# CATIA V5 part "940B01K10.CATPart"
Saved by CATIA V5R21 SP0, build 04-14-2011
Part number: 940B01K10
Bounding box of the stored display mesh (mm): x -8.25 to 387.75, y -7 to 7, z -25.901 to 9.099
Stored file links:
  C:\Users\ALI OZGUN\Desktop\alhan\940B01K10.CATPart
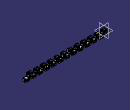
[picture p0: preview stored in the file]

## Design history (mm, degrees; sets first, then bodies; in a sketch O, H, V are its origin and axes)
Body1 (main body)
  Sketch1 on zx-plane, origin (0, 0, 0), H (-1, 0, 0), V (0, 0, 1)
    point P1 (-8.25, -8.9006)
    line L1 (-8.25, -7.9006) -> (-8, -7.6506)
    point P2 (-8, -7.6506)
    line L2 (-8, -7.6506) -> (-8, 6.6246)
    point P3 (-8, 6.6246)
    line L3 (-8, 6.6246) -> (-5.5251, 9.0994)
    point P4 (-5.5251, 9.0994)
    line L4 (-5.5251, 9.0994) -> (0, 9.0994)
    point P5 (0, 9.0994)
    line L5 (-8.25, -7.9006) -> (-8.25, -11.9006)
    point P6 (-8.25, -11.9006)
    line L6 (-8.25, -11.9006) -> (-5, -8.6506)
    point P7 (-3.25, -6.9006)
    line L7 (-5, -6.9006) -> (0, -6.9006)
    point P8 (0, -6.9006)
    line L8 (0, 6.2994) -> (-4.0825, 6.2994)
    point P9 (-4.0825, 6.2994)
    line L9 (-4.0825, 6.2994) -> (-5.2, 5.1819)
    point P10 (-5.2, 5.1819)
    line L10 (-5.2, 5.1819) -> (-5.2, -3.4006)
    point P11 (-5.2, -3.4006)
    line L11 (-5.2, -3.4006) -> (0, -3.4006)
    point P12 (0, -3.4006)
    point P13 (-8.25, -7.9006)
    point P14 (8, -7.6506)
    point P15 (8.25, -7.9006)
    line L12 (8.25, -7.9006) -> (8, -7.6506)
    point P16 (8, 6.6246)
    line L13 (8, -7.6506) -> (8, 6.6246)
    point P17 (5.5251, 9.0994)
    line L14 (8, 6.6246) -> (5.5251, 9.0994)
    point P18 (8.25, -11.9006)
    line L15 (8.25, -7.9006) -> (8.25, -11.9006)
    point P19 (3.25, -6.9006)
    line L16 (8.25, -11.9006) -> (5, -8.6506)
    point P20 (5.2, 5.1819)
    point P21 (4.0825, 6.2994)
    line L17 (4.0825, 6.2994) -> (5.2, 5.1819)
    point P22 (5.2, -3.4006)
    line L18 (5.2, 5.1819) -> (5.2, -3.4006)
    point P23 (0, -6.9006)
    line L19 (5, -6.9006) -> (0, -6.9006)
    point P24 (0, -3.4006)
    line L20 (5.2, -3.4006) -> (0, -3.4006)
    line L21 (0, 6.2994) -> (4.0825, 6.2994)
    point P25 (0, 9.0994)
    line L22 (5.5251, 9.0994) -> (0, 9.0994)
    point P26 (0, 6.2994)
    point P27 (0, 6.2994)
    line L23 (-5, -6.9006) -> (-5, -8.6506)
    line L24 (5, -6.9006) -> (5, -8.6506)
    distance L2 V = 8
    angle L3 L2 = 135
    distance L4 H = 9.0994
    distance L8 L4 = 2.8
    distance L10 L2 = 2.8
    distance L11 L7 = 3.5
    distance L9 L3 = 3
    length L3 = 3.5
    distance L4 L7 = 16
    distance L4 P6 = 21
    distance L5 L2 = 0.25
    length L5 = 4
    distance L23 L2 = 3
    vertical: L2 V, L5 V, L10 V, L23 V
    parallelism: L3 L1, L6 L1
    horizontal: L4 H, L7 H, L8 H, L11 H
    coincidence: P5 V, P8 V, P12 V, P1 L5, P26 V, P27 V, P5 P25, P8 P23, P12 P24, P26 P27, P7 L7, P7 L6, P19 L16, P19 L19
    symmetry: P2 P14 V, P13 P15 V, L1 L12 V, P3 P16 V, L2 L13 V, P4 P17 V, L3 L14 V, P6 P18 V, L5 L15 V, P7 P19 V, L6 L16 V, P10 P20 V, P9 P21 V, L9 L17 V, P11 P22 V, L10 L18 V, P8 P23 V, L7 L19 V, P12 P24 V, L11 L20 V, L8 L21 V, P5 P25 V, L4 L22 V, L23 L24 V
  Pad1: profile Sketch1, direction (0, 1, 0), length 7, mirrored extent
  Fillet1: radius 3, on edge [face of Pad1 from Sketch1.L22 | face of Pad1 from Sketch1.L14]; edge [face of Pad1 from Sketch1.L3 | face of Pad1 from Sketch1.L4]; edge [face of Pad1 from Sketch1.L2 | face of Pad1 from Sketch1.L3]; edge [face of Pad1 from Sketch1.L14 | face of Pad1 from Sketch1.L13]
  Fillet2: radius 1, on edge [face of Pad1 from Sketch1.L17 | face of Pad1 from Sketch1.L21]; edge [face of Pad1 from Sketch1.L18 | face of Pad1 from Sketch1.L17]; edge [face of Pad1 from Sketch1.L8 | face of Pad1 from Sketch1.L9]; edge [face of Pad1 from Sketch1.L9 | face of Pad1 from Sketch1.L10]
  Fillet3: radius 2, on edge [face of Pad1 from Sketch1.L23 | face of Pad1 from Sketch1.L6]; edge [face of Pad1 from Sketch1.L16 | face of Pad1 from Sketch1.L24]
  Fillet4: radius 1.5, on edge [face of Pad1 from Sketch1.L20 | face of Pad1 from Sketch1.L18]; edge [face of Pad1 from Sketch1.L10 | face of Pad1 from Sketch1.L11]
  Body2
    Sketch2 on zx-plane, origin (0, 0, 0), H (-1, 0, 0), V (0, 0, 1)
      line L1 (-8.25, -7.9006) -> (-10.25, -9.9006)
      line L2 (-10.25, -9.9006) -> (-16.5, -9.9006)
      line L3 (-8.25, -11.9006) -> (-8.5, -12.1506)
      line L4 (-8.5, -12.1506) -> (-8.5, -25.9006)
      line L5 (-8.5, -25.9006) -> (-16.5, -25.9006)
      line L6 (-16.5, -22.7006) -> (-11.3, -22.7006)
      line L7 (-11.3, -22.7006) -> (-11.3, -13.1006)
      line L8 (-11.3, -13.1006) -> (-16.5, -13.1006)
      axis line L9 (-16.5, -4.8689) -> (-16.5, -27.5881)
      point P6 (-16.5, -9.9006)
      point P7 (-16.5, -13.1006)
      point P8 (-16.5, -22.7006)
      point P9 (-16.5, -25.9006)
      reference projected line E1 (0, 9.0994) -> (-5.5251, 9.0994) from edge [face of Pad1 from Sketch1.L4 | end face of Pad1]
      reference projected line E2 (-8.325, -11.9756) -> (-4.925, -8.5756) from edge [face of Pad1 from Sketch1.L6 | end face of Pad1]
      reference projected line E3 (-7.925, -7.5756) -> (-8.325, -7.9756) from edge [face of Pad1 from Sketch1.L1 | end face of Pad1]
      projected line E4 (-8.25, -7.9006) -> (-8.25, -11.9006) from edge [face of Pad1 from Sketch1.L5 | end face of Pad1]
      projected line E5 (-8.25, -7.9006) -> (-8.25, -11.9006) from edge [face of Pad1 from Sketch1.L5 | end face of Pad1]
      reference projected line E6 (-8, 6.6246) -> (-8, -7.6506) from edge [face of Pad1 from Sketch1.L2 | end face of Pad1]
      line L10 (-16.5, -9.9006) -> (-16.5, -13.1006)
      line L11 (-16.5, -22.7006) -> (-16.5, -25.9006)
      distance L5 E1 = 35
      distance L2 L5 = 16
      distance L8 L2 = 3.2
      distance L6 L5 = 3.2
      distance L7 L4 = 2.8
      distance L4 E6 = 0.5
      distance L4 L9 = 8
      horizontal: L2 H, L5 H, L6 H, L8 H
      vertical: L4 V, L7 V, L9 V, L10 V, L11 V
      coincidence: P6 L9, P7 L9, P8 L9, P9 L9, L3 E2, L1 E3
    Pad2: profile Sketch2, direction (0, 1, 0), length 7, mirrored extent
    Mirror1: of the body so far, about face of Pad2 from Sketch2.L10
    Fillet5: radius 1.5, on edge [face of Pad2 | face of Mirror1] (x2); edge [face of Pad2 from Sketch2.L4 | face of Pad2]; edge [face of Mirror1 | face of Pad2] (x2); edge [face of Pad2 | face of Pad2 from Sketch2.L1]; edge [face of Pad2 from Sketch2.L7 | face of Pad2]; edge [face of Pad2 | face of Pad2 from Sketch2.L7]
  Add1: tool Body2
  RemoveFace1: RemoveFaces (face of Fillet5; face of Fillet1; face of Fillet5; face of Fillet1)
  Thickness1: Face (face of Pad2 from Sketch2.L4; face of Mirror1; face of Pad1 from Sketch1.L2; face of Pad1 from Sketch1.L13), Thickness 0.2
  RectPattern1: of the body so far, direction 1 instances 12, spacing 33, along edge [face of Pad1 | face of Pad2]
  Sketch3 on yz-plane, origin (0, 0, 0), H (0, 1, 0), V (0, 0, 1)
    construction line L1 (0, 4.5994) -> (0, -1.4006)
    point P1 (0, 4.5994)
    line L2 (2.5, 4.5994) -> (2.5, -1.4006)
    line L3 (-2.5, -1.4006) -> (-2.5, 4.5994)
    arc A1 centre (0, -1.4006) radius 2.5 from (2.5, -1.4006) to (-2.5, -1.4006) cw
    arc A2 centre (0, 4.5994) radius 2.5 from (-2.5, 4.5994) to (2.5, 4.5994) cw
    construction line L4 (0, -14.8006) -> (0, -20.8006)
    point P7 (0, -14.8006)
    point P8 (0, -20.8006)
    line L5 (2.5, -14.8006) -> (2.5, -20.8006)
    line L6 (-2.5, -20.8006) -> (-2.5, -14.8006)
    arc A3 centre (0, -20.8006) radius 2.5 from (2.5, -20.8006) to (-2.5, -20.8006) cw
    arc A4 centre (0, -14.8006) radius 2.5 from (-2.5, -14.8006) to (2.5, -14.8006) cw
    reference projected line E1 (-7, 9.0994) -> (7, 9.0994) from edge [face of Pad1 from Sketch1.L22 | face of Fillet1]
    distance L1 L2 = 2.5
    distance L4 L5 = 2.5
    length L1 = 6
    length L4 = 6
    distance A2 E1 = 2
    distance P8 P1 = 25.4
    coincidence: P1 V, P7 V
    vertical: L1 V, L4 V
    tangency: A1 L2, A2 L2, A1 L3, A2 L3, A3 L5, A4 L5, A3 L6, A4 L6
  Pocket1: profile Sketch3, direction (-1, 0, 0), through (limit type 3), opposite side through (limit type 3)
  Sketch4 on yz-plane, origin (0, 0, 0), H (0, 1, 0), V (0, 0, 1)
    point P1 (-8.4771, 2.8138)
    line L1 (-8.4771, 2.8138) -> (-2.6189, 9.5743)
    point P2 (-2.6189, 9.5743)
    line L2 (-2.6189, 9.5743) -> (2.2825, 9.5743)
    point P3 (2.2825, 9.5743)
    line L3 (2.2825, 9.5743) -> (8.6297, 3.2271)
    point P4 (8.6297, 3.2271)
    reference projected line E1 (-7, 9.0994) -> (-7, 8.2208) from edge [face of RectPattern1 | face of RectPattern1]
    point P5 (-7, 9.0994)
    point P6 (-7, 8.2208)
    reference projected line E2 (7, 8.2208) -> (7, 9.0994) from edge [face of RectPattern1 | face of RectPattern1]
    point P7 (7, 8.2208)
    point P8 (7, 9.0994)
    reference projected line E3 (-7, 9.0994) -> (7, 9.0994) from edge [face of RectPattern1 | face of RectPattern1]
    reference projected line E4 (-7, 9.0994) -> (7, 9.0994) from edge [face of RectPattern1 | face of RectPattern1]
    construction line L4 (7, -25.9006) -> (7, 8.6601)
    point P11 (7, 8.6601)
    axis line L5 (7, -8.6202) -> (39.3545, -8.6202)
    point P12 (7, -8.6202)
    point P14 (-8.4771, -20.0542)
    point P15 (-2.6189, -26.8148)
    point P16 (2.2825, -26.8148)
    point P17 (8.6297, -20.4676)
    point P18 (-7, -25.4612)
    point P19 (-7, -26.3399)
    point P20 (7, -26.3399)
    point P21 (7, -25.4612)
    point P22 (7, -25.9006)
    line L6 (-8.4771, -20.0542) -> (-2.6189, -26.8148)
    line L7 (-2.6189, -26.8148) -> (2.2825, -26.8148)
    line L8 (2.2825, -26.8148) -> (8.6297, -20.4676)
    construction line L9 (-7, -26.3399) -> (-7, -25.4612)
    construction line L10 (7, -25.4612) -> (7, -26.3399)
    line L11 (8.6297, 3.2271) -> (8.6297, -20.4676)
    line L12 (-8.4771, 2.8138) -> (-8.4771, -20.0542)
    distance L1 P5 = 3
    distance L3 P8 = 3
    angle L3 E3 = 45
    angle L1 E4 = 49.0902
    horizontal: L2 H, L5 H
    midpoint: P11 E2, P12 L4
    vertical: L4 V, L11 V, L12 V
    symmetry: P1 P14 L5, P2 P15 L5, P3 P16 L5, P4 P17 L5, P6 P18 L5, P5 P19 L5, E1 L9 L5, P8 P20 L5, P7 P21 L5, E2 L10 L5, P11 P22 L5, L1 L6 L5, L2 L7 L5, L3 L8 L5
  Pocket2: profile Sketch4, direction (-1, 0, 0), through (limit type 3), opposite side length 517, outer side
Body3
  Solid1: linked copy from another document
  Translate1: ToTransfor Solid1, Direction xy-plane, Length 19.4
